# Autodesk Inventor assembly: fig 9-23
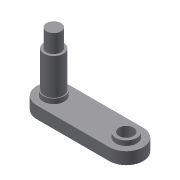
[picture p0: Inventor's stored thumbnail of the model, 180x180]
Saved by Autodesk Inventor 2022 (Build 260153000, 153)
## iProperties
Created: 2002-01
Part Number: fig 9-23
Document SubType Name: Assembly
Designer: ***
Control State: 0
Master: False
Checked Out: False
Shininess: 64.0
Length Units: 11269
Angle Units: 11279
Time Units: 11290
Mass Units: 11283
Length Display Precision: 3
Angle Display Precision: 2
Density: 0.0
Volumn: 0.0
Area: 0.0
PropertySet Name: Model Information
Author: ***
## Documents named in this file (3)
- D:\PROJECTS_2021\Resources\Part Files\c09_Inv_2022_prt\fig 9-23.iam
- D:\PROJECTS_2021\Resources\Part Files\c09_Inv_2022_prt\Part5.ipt
- D:\PROJECTS_2021\Resources\Part Files\c09_Inv_2022_prt\Part6.ipt
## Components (2 placed, 2 different names)
1. Part5:1 — Insert:1
2. Part6:1 — Insert:1
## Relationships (1: Insert 1)
- Insert:1: Part5:1 ↔ Part6:1
